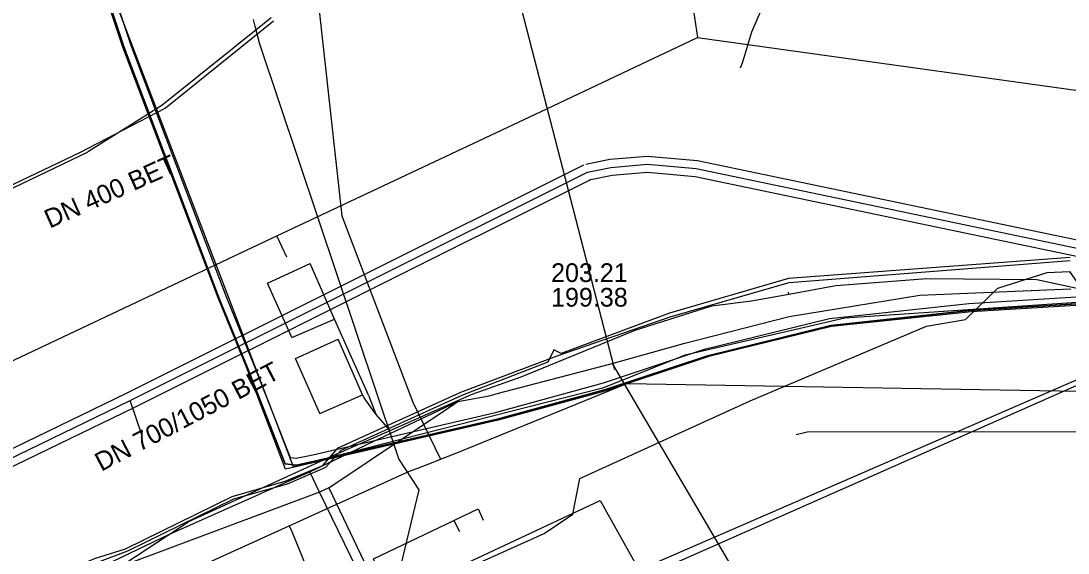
# Model space of a CAD drawing. Extents: x -600309 to -598967, y -1161267 to -1160292.
# Drawn here: x -599327.71 to -599282.99, y -1161240.63 to -1161217.9 of the extents above; entities that cross this region are included whole.
import ezdxf

# ---------------------------------------------------------------- set-up
doc = ezdxf.new("R2010")
doc.units = 0
for name, color, linetype in [('Vrstva 10', 7, 'Continuous'), ('Vrstva 12', 7, 'Continuous'), ('Vrstva 13', 7, 'Continuous'), ('Vrstva 16', 7, 'Continuous'), ('Vrstva 19', 7, 'Continuous'), ('Vrstva 42', 7, 'Continuous'), ('Vrstva 44', 7, 'Continuous'), ('Vrstva 55', 7, 'Continuous'), ('Vrstva 58', 7, 'Continuous'), ('Vrstva 9', 7, 'Continuous')]:
    doc.layers.add(name, color=color, linetype=linetype)

msp = doc.modelspace()

# ---------------------------------------------------------------- linework, layer by layer
at = {"layer": 'Vrstva 10'}
for points in [[(-599303.586, -1161224.015), (-599302.565, -1161223.81), (-599300.956, -1161223.673), (-599298.819, -1161223.863), (-599269.258, -1161230.047), (-599235.407, -1161238.263), (-599234.478, -1161238.388), (-599233.878, -1161238.413), (-599233.122, -1161238.174)], [(-599334.222, -1161239.139), (-599323.199, -1161233.802), (-599303.673, -1161224.045)], [(-599232.911, -1161238.841), (-599233.784, -1161239.118), (-599234.54, -1161239.086), (-599235.536, -1161238.952), (-599269.412, -1161230.73), (-599298.922, -1161224.556), (-599300.958, -1161224.376), (-599302.466, -1161224.504), (-599303.448, -1161224.701)], [(-599303.361, -1161224.671), (-599322.89, -1161234.431), (-599333.916, -1161239.769)]]:
    msp.add_lwpolyline(points, dxfattribs=at)
at = {"layer": 'Vrstva 12'}
for points in [[(-599299.36, -1161231.67), (-599294.9, -1161230.52), (-599289.33, -1161229.62)], [(-599289.33, -1161229.62), (-599282.88, -1161229.35)], [(-599302.46, -1161232.53), (-599299.36, -1161231.67)], [(-599307.31, -1161233.8), (-599302.46, -1161232.53)], [(-599302.46, -1161232.53), (-599297.39, -1161241.16), (-599292.49, -1161249.07)], [(-599311.85, -1161242.54), (-599302.97, -1161238.39), (-599301.29, -1161241.39), (-599300.34, -1161243.34), (-599297.2, -1161250.02), (-599277.53, -1161241.21), (-599271.89, -1161238.85), (-599269.41, -1161237.59), (-599266.17, -1161236.32), (-599265.34, -1161236.38), (-599259.12, -1161234.24), (-599258.19, -1161235.64), (-599257.6, -1161236.83), (-599257.57, -1161237.59), (-599256.25, -1161240.7)], [(-599311.67, -1161235.4), (-599309.06, -1161234.15)], [(-599309.9, -1161234.72), (-599309.06, -1161234.15)], [(-599309.06, -1161234.15), (-599307.72, -1161233.91)], [(-599307.72, -1161233.91), (-599307.31, -1161233.8)], [(-599311.12, -1161235.53), (-599309.9, -1161234.72)], [(-599314.56, -1161237.84), (-599311.12, -1161235.53)], [(-599312.67, -1161235.87), (-599311.67, -1161235.4)], [(-599315.38, -1161237.16), (-599312.67, -1161235.87)], [(-599316.74, -1161237.76), (-599315.38, -1161237.16)], [(-599314.96, -1161238.03), (-599315.38, -1161237.16)], [(-599317.04, -1161237.9), (-599316.74, -1161237.76)], [(-599314.96, -1161238.03), (-599323.45, -1161241.2), (-599324.27, -1161241.78)], [(-599324.07, -1161241.12), (-599321.4, -1161239.83), (-599317.49, -1161238.1)], [(-599317.49, -1161238.1), (-599317.25, -1161237.99)], [(-599317.25, -1161237.99), (-599317.04, -1161237.9)], [(-599314.56, -1161237.84), (-599314.96, -1161238.03)], [(-599309.56, -1161248.3), (-599310.41, -1161247.38), (-599314.96, -1161238.03)], [(-599314.56, -1161237.84), (-599309.56, -1161248.3)], [(-599309.22, -1161239.24), (-599308.18, -1161238.74), (-599307.97, -1161239.22)], [(-599311.85, -1161242.54), (-599312.66, -1161240.88), (-599309.22, -1161239.24)], [(-599309.22, -1161239.24), (-599308.98, -1161239.71)]]:
    msp.add_lwpolyline(points, dxfattribs=at)
at = {"layer": 'Vrstva 13'}
for p, q in [((-599310.972, -1161234.182), (-599310.039, -1161236.119)), ((-599310.039, -1161236.119), (-599309.798, -1161236.623)), ((-599309.798, -1161236.623), (-599309.236, -1161236.401)), ((-599310.172, -1161236.769), (-599309.798, -1161236.623))]:
    msp.add_line(p, q, dxfattribs=at)
for points in [[(-599323.681, -1161152.349), (-599318.53, -1161185.207), (-599314.01, -1161226.23), (-599310.972, -1161234.182)], [(-599309.236, -1161236.401), (-599308.711, -1161236.195), (-599301.83, -1161233.38), (-599280.01, -1161233.75), (-599252.11, -1161233.94), (-599245.192, -1161234.386)], [(-599379.539, -1161267.031), (-599372.088, -1161257.728), (-599359.297, -1161251.863), (-599357.798, -1161251.176), (-599338.48, -1161242.32), (-599323.02, -1161242.54), (-599316.251, -1161239.468), (-599311.113, -1161237.136), (-599310.694, -1161236.973), (-599310.172, -1161236.769)], [(-599316.251, -1161239.468), (-599316.139, -1161239.714), (-599312.036, -1161249.778)]]:
    msp.add_lwpolyline(points, dxfattribs=at)
at = {"layer": 'Vrstva 16'}
for points in [[(-599302.349, -1161232.808), (-599308.99, -1161207.05), (-599324.87, -1161145.39), (-599327.49, -1161135.23)], [(-599246.47, -1161236.19), (-599257.64, -1161235.42), (-599294.13, -1161235.47), (-599294.604, -1161235.577)]]:
    msp.add_lwpolyline(points, dxfattribs=at)
at = {"layer": 'Vrstva 19'}
for points in [[(-599310.71, -1161237.93), (-599311.57, -1161236.61), (-599311.702, -1161236.217), (-599317.51, -1161218.89), (-599317.71, -1161218.122), (-599317.785, -1161217.833)], [(-599377.61, -1161267.031), (-599371.17, -1161259.3), (-599342.2, -1161246.17), (-599321.88, -1161248.22), (-599321.1, -1161247.94), (-599312.06, -1161243.57), (-599310.71, -1161237.93)]]:
    msp.add_lwpolyline(points, dxfattribs=at)
at = {"layer": 'Vrstva 42'}
for p, q in [((-599317.185, -1161229.095), (-599315.362, -1161228.257)), ((-599316.147, -1161231.428), (-599317.185, -1161229.095)), ((-599294.924, -1161229.569), (-599294.94, -1161229.48)), ((-599316.147, -1161231.428), (-599314.314, -1161230.632)), ((-599315.989, -1161232.32), (-599314.17, -1161231.495)), ((-599314.945, -1161234.661), (-599315.989, -1161232.32)), ((-599311.941, -1161235.392), (-599312.554, -1161234.69)), ((-599324.73, -1161242.02), (-599320.54, -1161239.28))]:
    msp.add_line(p, q, dxfattribs=at)
for points in [[(-599281.041, -1161229.89), (-599287.207, -1161230.27), (-599293.124, -1161230.908), (-599298.438, -1161232.214), (-599302.746, -1161233.644), (-599307.373, -1161234.915), (-599315.171, -1161236.703), (-599315.94, -1161236.879), (-599316.43, -1161236.823), (-599318.049, -1161232.676), (-599319.24, -1161229.755), (-599321.806, -1161222.976), (-599323.301, -1161219.03), (-599325.346, -1161212.886), (-599325.581, -1161211.397), (-599325.494, -1161210.058), (-599325.389, -1161209.502), (-599325.06, -1161206.98), (-599320.177, -1161197.637), (-599318.677, -1161194.767), (-599319.849, -1161188.588), (-599323.269, -1161173.566), (-599323.242, -1161172.673), (-599317.762, -1161171.228)], [(-599317.762, -1161171.228), (-599323.242, -1161172.673), (-599323.269, -1161173.566), (-599319.849, -1161188.588), (-599318.677, -1161194.767), (-599320.177, -1161197.637), (-599325.06, -1161206.98), (-599325.389, -1161209.502), (-599325.494, -1161210.058), (-599325.581, -1161211.397), (-599325.346, -1161212.886), (-599323.301, -1161219.03), (-599321.806, -1161222.976), (-599319.24, -1161229.755), (-599318.049, -1161232.676), (-599316.43, -1161236.823), (-599315.94, -1161236.879), (-599315.171, -1161236.703), (-599307.373, -1161234.915), (-599302.746, -1161233.644), (-599298.438, -1161232.214), (-599293.124, -1161230.908), (-599287.207, -1161230.27), (-599281.041, -1161229.89)], [(-599354.35, -1161224.035), (-599353.87, -1161223.93), (-599350.98, -1161224.32), (-599350.984, -1161224.313), (-599341.004, -1161218.864), (-599338.515, -1161216.814), (-599325.587, -1161209.739), (-599325.092, -1161209.468), (-599325.196, -1161210.096), (-599325.279, -1161211.383), (-599325.054, -1161212.814), (-599323.019, -1161218.93), (-599321.517, -1161222.89), (-599318.96, -1161229.645), (-599317.747, -1161232.635), (-599316.216, -1161236.545), (-599315.956, -1161236.575), (-599315.252, -1161236.429), (-599307.447, -1161234.625), (-599302.834, -1161233.356), (-599298.522, -1161231.926), (-599293.176, -1161230.612), (-599287.233, -1161229.97), (-599281.039, -1161229.59)], [(-599354.35, -1161224.035), (-599353.87, -1161223.93), (-599350.98, -1161224.32), (-599350.984, -1161224.313), (-599341.004, -1161218.864), (-599338.515, -1161216.814), (-599325.587, -1161209.739), (-599325.092, -1161209.468), (-599325.196, -1161210.096), (-599325.279, -1161211.383), (-599325.054, -1161212.814), (-599323.019, -1161218.93), (-599321.517, -1161222.89), (-599318.96, -1161229.645), (-599317.747, -1161232.635), (-599316.216, -1161236.545), (-599315.956, -1161236.575), (-599315.252, -1161236.429), (-599307.447, -1161234.625), (-599302.834, -1161233.356), (-599298.522, -1161231.926), (-599293.176, -1161230.612), (-599287.233, -1161229.97), (-599281.039, -1161229.59)], [(-599354.35, -1161224.035), (-599353.87, -1161223.93), (-599350.98, -1161224.32), (-599350.984, -1161224.313), (-599341.004, -1161218.864), (-599338.515, -1161216.814), (-599325.587, -1161209.739), (-599325.092, -1161209.468), (-599325.196, -1161210.096), (-599325.279, -1161211.383), (-599325.054, -1161212.814), (-599323.019, -1161218.93), (-599321.517, -1161222.89), (-599318.96, -1161229.645), (-599317.747, -1161232.635), (-599316.216, -1161236.545), (-599315.956, -1161236.575), (-599315.252, -1161236.429), (-599307.447, -1161234.625), (-599302.834, -1161233.356), (-599298.522, -1161231.926), (-599293.176, -1161230.612), (-599287.233, -1161229.97), (-599281.039, -1161229.59)], [(-599324.494, -1161210.318), (-599324.993, -1161209.83), (-599325.482, -1161209.987), (-599325.494, -1161210.058), (-599325.581, -1161211.397), (-599325.346, -1161212.886), (-599323.301, -1161219.03), (-599321.806, -1161222.976), (-599319.24, -1161229.755), (-599318.049, -1161232.676), (-599316.43, -1161236.823), (-599315.94, -1161236.879), (-599315.171, -1161236.703), (-599307.373, -1161234.915), (-599302.746, -1161233.644), (-599298.438, -1161232.214), (-599293.124, -1161230.908), (-599287.207, -1161230.27), (-599281.041, -1161229.89)], [(-599324.494, -1161210.318), (-599324.993, -1161209.83), (-599325.482, -1161209.987), (-599325.494, -1161210.058), (-599325.581, -1161211.397), (-599325.346, -1161212.886), (-599323.301, -1161219.03), (-599321.806, -1161222.976), (-599319.24, -1161229.755), (-599318.049, -1161232.676), (-599316.43, -1161236.823), (-599315.94, -1161236.879), (-599315.171, -1161236.703), (-599307.373, -1161234.915), (-599302.746, -1161233.644), (-599298.438, -1161232.214), (-599293.124, -1161230.908), (-599287.207, -1161230.27), (-599281.041, -1161229.89)], [(-599281.033, -1161229.951), (-599287.119, -1161230.329), (-599293.095, -1161230.953), (-599298.342, -1161232.229), (-599302.774, -1161233.715), (-599307.324, -1161234.957), (-599316.412, -1161237.043), (-599318.082, -1161232.685), (-599319.282, -1161229.726), (-599321.852, -1161222.998), (-599323.365, -1161219.02), (-599325.388, -1161212.901)], [(-599325.346, -1161212.886), (-599323.301, -1161219.03), (-599321.806, -1161222.976), (-599319.24, -1161229.755), (-599318.049, -1161232.676), (-599316.43, -1161236.823), (-599315.94, -1161236.879), (-599315.171, -1161236.703), (-599307.373, -1161234.915), (-599302.746, -1161233.644), (-599298.438, -1161232.214), (-599293.124, -1161230.908), (-599287.207, -1161230.27), (-599281.041, -1161229.89)], [(-599325.346, -1161212.886), (-599323.301, -1161219.03), (-599321.806, -1161222.976), (-599319.24, -1161229.755), (-599318.049, -1161232.676), (-599316.43, -1161236.823), (-599315.94, -1161236.879), (-599315.171, -1161236.703), (-599307.373, -1161234.915), (-599302.746, -1161233.644), (-599298.438, -1161232.214), (-599293.124, -1161230.908), (-599287.207, -1161230.27), (-599281.041, -1161229.89)], [(-599325.054, -1161212.814), (-599323.019, -1161218.93), (-599321.517, -1161222.89), (-599318.96, -1161229.645), (-599317.747, -1161232.635), (-599316.216, -1161236.545), (-599315.956, -1161236.575), (-599315.252, -1161236.429), (-599307.447, -1161234.625), (-599302.834, -1161233.356), (-599298.522, -1161231.926), (-599293.176, -1161230.612), (-599287.233, -1161229.97)], [(-599325.054, -1161212.814), (-599323.019, -1161218.93), (-599321.517, -1161222.89), (-599318.96, -1161229.645), (-599317.747, -1161232.635), (-599316.216, -1161236.545), (-599315.956, -1161236.575), (-599315.252, -1161236.429), (-599307.447, -1161234.625), (-599302.834, -1161233.356), (-599298.522, -1161231.926), (-599293.176, -1161230.612), (-599287.233, -1161229.97), (-599281.039, -1161229.59)], [(-599325.054, -1161212.814), (-599323.019, -1161218.93), (-599321.517, -1161222.89), (-599318.96, -1161229.645), (-599317.747, -1161232.635), (-599316.216, -1161236.545), (-599315.956, -1161236.575), (-599315.252, -1161236.429), (-599307.447, -1161234.625), (-599302.834, -1161233.356), (-599298.522, -1161231.926), (-599293.176, -1161230.612), (-599287.233, -1161229.97), (-599281.039, -1161229.59)], [(-599294.12, -1161214.278), (-599295.236, -1161215.407), (-599296.52, -1161218.383), (-599296.9, -1161219.657), (-599297, -1161219.92)], [(-599312.865, -1161233.892), (-599314.314, -1161230.632), (-599315.362, -1161228.257)], [(-599294.924, -1161229.569), (-599292.913, -1161229.199), (-599289.023, -1161228.909), (-599284.331, -1161228.941), (-599281.357, -1161229.589), (-599276.205, -1161229.837), (-599269.183, -1161230.378), (-599266.545, -1161230.732), (-599263.937, -1161231.022), (-599261.087, -1161231.501), (-599261.239, -1161230.1)], [(-599311.941, -1161235.392), (-599308.438, -1161233.842), (-599306.344, -1161233.096), (-599301.482, -1161231.105), (-599298.205, -1161230.073), (-599296.515, -1161229.861), (-599294.924, -1161229.569)], [(-599287.233, -1161229.97), (-599281.039, -1161229.59), (-599271.815, -1161230.301), (-599265.927, -1161231.054), (-599259.601, -1161231.863), (-599255.835, -1161232.878), (-599254.093, -1161234.988), (-599251.102, -1161241.051), (-599248.858, -1161247.351), (-599246.943, -1161252.939), (-599246.841, -1161253.236), (-599246.707, -1161253.195), (-599244.843, -1161252.625), (-599230.966, -1161248.274), (-599224.086, -1161245.855), (-599223.848, -1161245.926), (-599223.518, -1161246.105), (-599222.38, -1161246.804), (-599219.827, -1161252.523), (-599219.826, -1161252.528), (-599215.625, -1161264.197), (-599214.673, -1161267.031)], [(-599314.945, -1161234.661), (-599313.121, -1161233.868), (-599314.17, -1161231.495)], [(-599312.865, -1161233.892), (-599312.554, -1161234.69), (-599313.048, -1161233.993), (-599313.121, -1161233.868)], [(-599320.54, -1161239.28), (-599314.47, -1161236.51), (-599311.941, -1161235.392)]]:
    msp.add_lwpolyline(points, dxfattribs=at)
at = {"layer": 'Vrstva 44'}
for points in [[(-599366.069, -1161267.031), (-599362.318, -1161263.719), (-599355.989, -1161259.196), (-599351.968, -1161256.69), (-599341.07, -1161249.897), (-599334.833, -1161248.911), (-599330.525, -1161249.82), (-599325.411, -1161252.505), (-599323.501, -1161251.68), (-599320.31, -1161250.214), (-599304.027, -1161242.527), (-599277.227, -1161230.875), (-599258.651, -1161232.996)], [(-599365.678, -1161267.031), (-599362.107, -1161263.892), (-599355.811, -1161259.526), (-599351.866, -1161256.957), (-599340.91, -1161250.18), (-599334.806, -1161249.189), (-599330.57, -1161250.202), (-599325.414, -1161252.822), (-599323.331, -1161251.952), (-599320.227, -1161250.583), (-599303.909, -1161242.887), (-599277.202, -1161231.07), (-599258.787, -1161233.207)]]:
    msp.add_lwpolyline(points, dxfattribs=at)
at = {"layer": 'Vrstva 55'}
for points in [[(-599417.457, -1161267.031), (-599414.1, -1161265.46), (-599400.09, -1161258.8), (-599400.02, -1161258.73), (-599399.52, -1161258.24), (-599398.06, -1161257.9), (-599386.75, -1161252.6), (-599375.67, -1161247.44), (-599374.98, -1161247.12), (-599374.32, -1161246.47), (-599372.97, -1161246.28), (-599363.62, -1161241.76), (-599350.59, -1161235.7), (-599350.31, -1161235.49), (-599350.33, -1161235.4), (-599350.22, -1161235.42), (-599348.95, -1161234.48), (-599347.73, -1161234.36), (-599336.07, -1161228.87), (-599324.87, -1161223.51), (-599324.82, -1161223.47), (-599321.69, -1161221.5), (-599317.03, -1161217.76)], [(-599282.91, -1161228.01), (-599294.93, -1161228.9), (-599300.01, -1161230.38), (-599304.64, -1161232.1), (-599304.95, -1161231.95), (-599305.21, -1161232.47), (-599308.86, -1161233.89), (-599314.05, -1161236.25), (-599314.7, -1161236.98), (-599316.34, -1161237.68), (-599318.64, -1161238.33), (-599323.16, -1161240.55), (-599324.56, -1161241.07), (-599329.6, -1161243.3)]]:
    msp.add_lwpolyline(points, dxfattribs=at)
at = {"layer": 'Vrstva 58'}
for points in [[(-599281.357, -1161229.835), (-599292.528, -1161230.596), (-599299.35, -1161232.183), (-599302.873, -1161233.579), (-599316.074, -1161236.943), (-599324.547, -1161214.793)], [(-599417.759, -1161267.031), (-599414.19, -1161265.36), (-599400.58, -1161258.91), (-599399.55, -1161258.13), (-599398.11, -1161257.8), (-599386.82, -1161252.51), (-599375.79, -1161247.34), (-599374.41, -1161246.31), (-599373.09, -1161246.21), (-599363.69, -1161241.69), (-599350.67, -1161235.6), (-599349.01, -1161234.38), (-599347.96, -1161234.35), (-599338.87, -1161230.14), (-599336.18, -1161228.76), (-599325.17, -1161223.51), (-599321.55, -1161221.63), (-599316.93, -1161217.89)], [(-599417.759, -1161267.031), (-599414.19, -1161265.36), (-599400.58, -1161258.91), (-599399.55, -1161258.13), (-599398.11, -1161257.8), (-599386.82, -1161252.51), (-599375.79, -1161247.34), (-599374.41, -1161246.31), (-599373.09, -1161246.21), (-599363.69, -1161241.69), (-599350.67, -1161235.6), (-599349.01, -1161234.38), (-599347.96, -1161234.35), (-599338.87, -1161230.14), (-599336.18, -1161228.76), (-599325.17, -1161223.51), (-599321.55, -1161221.63), (-599316.93, -1161217.89)], [(-599380.446, -1161267.031), (-599379.78, -1161266.72), (-599372.89, -1161263.35), (-599364.51, -1161259.36), (-599363.92, -1161258.76), (-599363.03, -1161258.62), (-599356.28, -1161255.53), (-599354.8, -1161255), (-599353.69, -1161254.24), (-599346.89, -1161251.1), (-599332.92, -1161244.62), (-599331.22, -1161244.05), (-599329.61, -1161243.12), (-599324.57, -1161240.86), (-599323.24, -1161240.45), (-599318.69, -1161238.22), (-599316.43, -1161237.56), (-599314.82, -1161236.89), (-599314.16, -1161236.13), (-599308.93, -1161233.75), (-599304.81, -1161232.21), (-599299.98, -1161230.54), (-599294.9, -1161229.07), (-599282.9, -1161228.13)], [(-599380.446, -1161267.031), (-599379.78, -1161266.72), (-599372.89, -1161263.35), (-599364.51, -1161259.36), (-599363.92, -1161258.76), (-599363.03, -1161258.62), (-599356.28, -1161255.53), (-599354.8, -1161255), (-599353.69, -1161254.24), (-599346.89, -1161251.1), (-599332.92, -1161244.62), (-599331.22, -1161244.05), (-599329.61, -1161243.12), (-599324.57, -1161240.86), (-599323.24, -1161240.45), (-599318.69, -1161238.22), (-599316.43, -1161237.56), (-599314.82, -1161236.89), (-599314.16, -1161236.13), (-599308.93, -1161233.75), (-599304.81, -1161232.21), (-599299.98, -1161230.54), (-599294.9, -1161229.07), (-599282.9, -1161228.13)], [(-599311.01, -1161242.36), (-599310.3, -1161242.02), (-599305.37, -1161239.79), (-599304.14, -1161238.97), (-599303.84, -1161237.44), (-599296.57, -1161234.13), (-599289.04, -1161230.94), (-599287.37, -1161230.65), (-599286, -1161229.32), (-599283.89, -1161228.64), (-599282.94, -1161228.61), (-599282.6, -1161229.08), (-599273.43, -1161229.4), (-599271.05, -1161229.57), (-599265.76, -1161230.17), (-599260.07, -1161231.18), (-599255.76, -1161232.28), (-599254.76, -1161232.4), (-599254.31, -1161232.61), (-599253.46, -1161233.22), (-599252.17, -1161234.25), (-599251.36, -1161235.29), (-599250.23, -1161237.2), (-599249.88, -1161238.1)]]:
    msp.add_lwpolyline(points, dxfattribs=at)
at = {"layer": 'Vrstva 9'}
for p, q in [((-599304.067, -1161184.28), (-599298.813, -1161218.613)), ((-599316.35, -1161227.987), (-599316.776, -1161227.083)), ((-599322.542, -1161235.581), (-599323.044, -1161234.116))]:
    msp.add_line(p, q, dxfattribs=at)
for points in [[(-599331.646, -1161234.094), (-599316.776, -1161227.083), (-599305.253, -1161221.649), (-599298.813, -1161218.613)], [(-599298.813, -1161218.613), (-599272.954, -1161222.207), (-599267.209, -1161223.005)], [(-599334.069, -1161239.454), (-599323.044, -1161234.116), (-599303.517, -1161224.358)], [(-599303.517, -1161224.358), (-599302.515, -1161224.157), (-599300.957, -1161224.025), (-599298.871, -1161224.21), (-599269.335, -1161230.389), (-599235.472, -1161238.607), (-599234.509, -1161238.737), (-599233.831, -1161238.766), (-599233.017, -1161238.507)]]:
    msp.add_lwpolyline(points, dxfattribs=at)

# ---------------------------------------------------------------- texts
at = {"layer": 'Vrstva 12'}
for s, rotation, p in [('DN 400 BET', 24.1387, (-599326.482, -1161226.775)), ('DN 700/1050 BET', 27.6519, (-599324.281, -1161237.161))]:
    msp.add_text(s, height=0.8, rotation=rotation, dxfattribs=at).set_placement(p)
for s, p in [('203.21', (-599305.071, -1161229.053)), ('199.38', (-599305.071, -1161230.103))]:
    msp.add_text(s, height=0.8, dxfattribs=at).set_placement(p)

doc.saveas('drawing.dxf')
